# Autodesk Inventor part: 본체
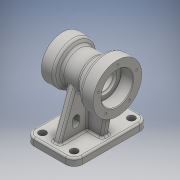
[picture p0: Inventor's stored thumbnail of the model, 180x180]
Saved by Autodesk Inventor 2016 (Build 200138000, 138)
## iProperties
Created: 2015-08
Part Number: 본체
Material: Generic
Document SubType Name: Modeling
Designer: Administrator
Density: 1 g/cm^3
Appearance: Default
Author: Administrator
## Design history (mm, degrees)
sketch "스케치1"
  geometry: L1 (45, 0)-(-45, 0); L2 (45, 0)-(45, 35); L3 (45, 35)-(25, 35); L4 (25, 35)-(19.804, 26); L5 (19.804, 26)-(-8.315, 26); L6 (-8.315, 26)-(-25, 40); L7 (-25, 40)-(-45, 40); L8 (-45, 40)-(-45, 0); 2 further points
  constraints: 16 end point, 2 coincident, 2 parallel, 2 perpendicular, 1 horizontal, 1 midpoint, 1 vertical
  dimensions: "d0" = 90 distance of L1.start L1.end; "d1" = 80 diameter of L7 L1; "d2" = 52 diameter of L5 L1; "d3" = 40 deg angle of L5 L6; "d4" = 20 distance from line of L6.end L8; "d5" = 20 distance of L2.end L3.end; "d6" = 60 deg angle of L4 L5; "d7" = 70 diameter of L3 L1
revolve "회전1" sketch "스케치1" stored, may be unused: angle "d8" = 90 deg
node "작업 평면1"
sketch "스케치2"
  geometry: L1 (-45, -61)-(35, -61); L2 (35, -61)-(35, 61); L3 (35, 61)-(-45, 61); L4 (-45, 61)-(-45, -61); L5 (-45, 35)-(-45, -35) reference; 4 further points
  constraints: 8 end point, 3 midpoint, 2 horizontal alignment, 2 parallel, 1 coincident, 1 horizontal, 1 perpendicular
  dimensions: "d10" = 122 distance of L3.end L1.start; "d11" = 80 distance of L2.end L3.end
extrude "돌출1" join sketch "스케치2" distance "d12" = 12; taper "d13" = 0 deg
sketch "스케치12"
  geometry: L1 (-11, -51)-(1, -51); L2 (1, -51)-(1, 51); L3 (1, 51)-(-11, 51); L4 (-11, 51)-(-11, -51); L5 (-45, -61)-(35, -61) reference; L6 (-45, 61)-(-45, -61) reference; L7 (35, 61)-(-45, 61) reference; L8 (35, -61)-(35, 61) reference; 5 further points
  constraints: 8 end point, 4 midpoint, 2 parallel, 1 horizontal, 1 horizontal alignment, 1 perpendicular, 1 vertical alignment
  dimensions: "d99" = 10 distance between parallel lines of L3 L7; "d100" = 12 distance of L2.end L3.end
extrude "돌출4" join sketch "스케치12" distance "d101" = 90; taper "d102" = 0 deg
sketch "스케치13"
  geometry: L1 (0, 102)-(-90, 102) reference; L2 (-71.185, 76.091)-(0, 102); L3 (0, 0)-(-90, 0) reference; L4 (-71.185, 25.909)-(0, 0); L5 (-90, 27.935)-(-90, 0) reference; L6 (-90, 0)-(-90, 27.935) reference; L7 (-90, 74.065)-(-90, 102) reference; L8 (-90, 102)-(-90, 74.065) reference; L9 (-90, 27.935)-(-90, 0) reference; L10 (0, 0)-(-90, 0); L11 (-90, 0)-(-90, 27.935); L12 (-90, 74.065)-(-90, 102); L13 (-90, 102)-(0, 102); A1 r 26 centre (-78, 51) between (-90, 27.935) and (-90, 74.065) reference; A2 r 26 centre (-78, 51) between (-90, 27.935) and (-71.185, 25.909); A3 r 26 centre (-78, 51) between (-71.185, 76.091) and (-90, 74.065); 1 further point
  constraints: 12 end point, 6 point on circle, 2 centre point, 1 coincident, 1 collinear, 1 horizontal, 1 perpendicular, 1 vertical
  dimensions: "d105" = 20 deg angle of L1 L2; "d106" = 20 deg angle of L3 L4
extrude "돌출5" cut sketch "스케치13" stored distance "d107" = 90; taper "d108" = 0 deg
sketch "스케치4"
  geometry: L1 (-45, -40)-(-25, -40) reference; L2 (-31.7, -40)-(-25, -78); L3 (-35, -78)-(45, -78) reference; L4 (-35, -90)-(-35, -78) reference; 1 further point
  constraints: 2 end point, 2 point on line
  dimensions: "d20" = 80 deg angle of L3 L2; "d21" = 10 distance from line of L2.end L4
feature "리브1" sketch "스케치4" dims "d22" = 1, "d23" = 12, "d24" = 0, "d25" = 0, "d26" = 1, "d27" = 1
sketch "스케치5"
  geometry: L1 (25, -35)-(45, -35) reference; L2 (35, -35)-(35, -78); L3 (-35, -78)-(45, -78) reference; L4 (45, -90)-(45, -78) reference; 1 further point
  constraints: 2 end point, 1 midpoint, 1 point on line, 1 vertical
  dimensions: "d28" = 10 distance between parallel lines of L2 L4
feature "리브2" sketch "스케치5" dims "d29" = 1, "d30" = 12, "d31" = 0, "d32" = 0, "d33" = 1, "d34" = 1
sketch "스케치6"
  geometry: L1 (-45, 0)-(45, 0); L2 (-45, -40)-(-45, 40) reference; L3 (45, -35)-(45, 35) reference; L4 (-45, 0)-(-45, 26); L5 (-45, 26)-(-25.3, 26); L6 (-25, 25.7)-(-25, 19); L7 (-25, 19)-(-25, 19); L8 (-22, 16)-(-22, 16); L9 (-22, 16)-(28, 16); L10 (28, 16)-(28, 19.7); L11 (28.3, 20)-(45, 20); L12 (45, 20)-(45, 0); A1 r 0.3 centre (-25.3, 25.7) between (-25, 25.7) and (-25.3, 26); A2 r 3 centre (-25, 16) between (-22, 16) and (-25, 19); A3 r 0.3 centre (28.3, 19.7) between (28.3, 20) and (28, 19.7); 2 further points
  constraints: 20 end point, 6 perpendicular, 6 point on circle, 6 tangent, 3 centre point, 3 midpoint, 2 coincident, 2 horizontal, 2 point on line, 1 collinear
  dimensions: "d35" = 40 diameter of L11 L1; "d36" = 32 diameter of L9 L1; "d37" = 17 distance between parallel lines of L3 L10; "d38" = 52 diameter of L5 L1; "d39" = 38 diameter of L7 L1; "d40" = 20 distance between parallel lines of L4 L6; "d41" = 3 distance between parallel lines of L6 L8; "d42" = 0.3 radius of A1; "d43" = 3 radius of A2; "d44" = 0.3 radius of A3
revolve "회전2" sketch "스케치6" stored, may be unused: angle "d45" = 90 deg
sketch "스케치14"
  geometry: L1 (-24, -36)-(-18, -36); L2 (-18, -24)-(-24, -24); L3 (0, -57)-(0, -12) reference; A1 r 6 centre (-24, -30) between (-24, -24) and (-24, -36); A2 r 6 centre (-18, -30) between (-18, -36) and (-18, -24); 1 further point
  constraints: 4 end point, 4 point on circle, 4 tangent, 2 centre point, 1 horizontal alignment
  dimensions: "d109" = 12 diameter of A1; "d110" = 12 diameter of A2; "d111" = 18 dimension on A2 A1; "d112" = 24 vertical distance of A1.centre point (-78, -6); "d113" = 18 distance from line of L3 A2.centre
extrude "돌출6" cut sketch "스케치14" stored distance "d114" = 90; taper "d115" = 0 deg
fillet "모깎기1" dims "d57" = 14
sketch "스케치8"
  geometry: A1 r 14 centre (-31, -47) between (-45, -47) and (-31, -61) reference; A2 r 14 centre (-31, 47) between (-31, 61) and (-45, 47) reference; A3 r 14 centre (21, 47) between (35, 47) and (21, 61) reference; A4 r 14 centre (21, -47) between (21, -61) and (35, -47) reference; 5 further points
  constraints: 4 coincident
hole "구멍1" sketch "스케치8" at (-31, -47), (-31, 47), (21, 47), (21, -47) diameter "d58" = 12; stored, may be unused: countersink angle "d62" = 90 deg, drill point angle "d64" = 118 deg; dims "d59" = 6, "d60" = 4, "d61" = 2, "d63" = 8
sketch "스케치9" dims "d65" = 66
  geometry: 3 further points
  constraints: 2 horizontal alignment, 1 coincident, 2 other
hole "구멍2" sketch "스케치9" at (-33, 0) diameter "d66" = 3.242; stored, may be unused: countersink angle "d70" = 90 deg, drill point angle "d72" = 118 deg; dims "d67" = 10, "d68" = 4, "d69" = 2, "d71" = 13
sketch "스케치10" dims "d76" = 54
  geometry: 3 further points
  constraints: 2 horizontal alignment, 1 coincident, 2 other
hole "구멍3" sketch "스케치10" at (27, 0) diameter "d77" = 3.242; stored, may be unused: countersink angle "d81" = 90 deg, drill point angle "d83" = 118 deg; dims "d78" = 10, "d79" = 4, "d80" = 2, "d82" = 13
chamfer "모따기1" distance "d87" = 1; stored, may be unused: second distance "d88" = 2, angle "d89" = 45 deg
fillet "모깎기2" dims "d90" = 5
fillet "모깎기3" dims "d91" = 3
fillet "모깎기4" dims "d92" = 3
fillet "모깎기5" dims "d93" = 3
fillet "모깎기6" dims "d94" = 3
sketch "스케치15"
  geometry: L1 (-16.928, -10.313)-(-16.928, -47.432) reference; L2 (39.072, -50.432)-(-12.928, -50.432) reference; 2 further points
  constraints: 1 other
  dimensions: "d118" = 16 distance from line of point (-0.928, -26.432) L1; "d119" = 24 distance from line of L2 point (-0.928, -26.432)
feature "엠보싱2" sketch "스케치15" dims "d0" = 90, "d1" = 80, "d2" = 52, "d3" = 40 deg, "d4" = 20, "d5" = 20, "d6" = 60 deg, "d7" = 70, "d120" = 0.5, "d121" = 0
fillet "모깎기7" dims "d122" = 3
fillet "모깎기8" dims "d123" = 3
fillet "모깎기9" dims "d124" = 3
fillet "모깎기10" dims "d125" = 3
fillet "모깎기11" dims "d126" = 5
node "솔리드1"
mirror "대칭1"
mirror "대칭2"
pattern_circular "원형 패턴1" dims angle "d74" = 360 deg
pattern_circular "원형 패턴2" dims angle "d85" = 360 deg
node "투영된 루프1"
node "투영된 루프2"
node "투영된 루프3"
